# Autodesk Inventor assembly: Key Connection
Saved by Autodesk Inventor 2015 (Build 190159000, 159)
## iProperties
Created: 2015-03
Part Number: Key Connection
Document SubType Name: Assembly
Designer: Uglješa
ClientObjectVersion: 1
Author: Uglješa
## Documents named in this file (1)
- C:\Users\Uglješa\Desktop\Turbokompr\Assembly1\Design Accelerator\Key Connection7.iam
